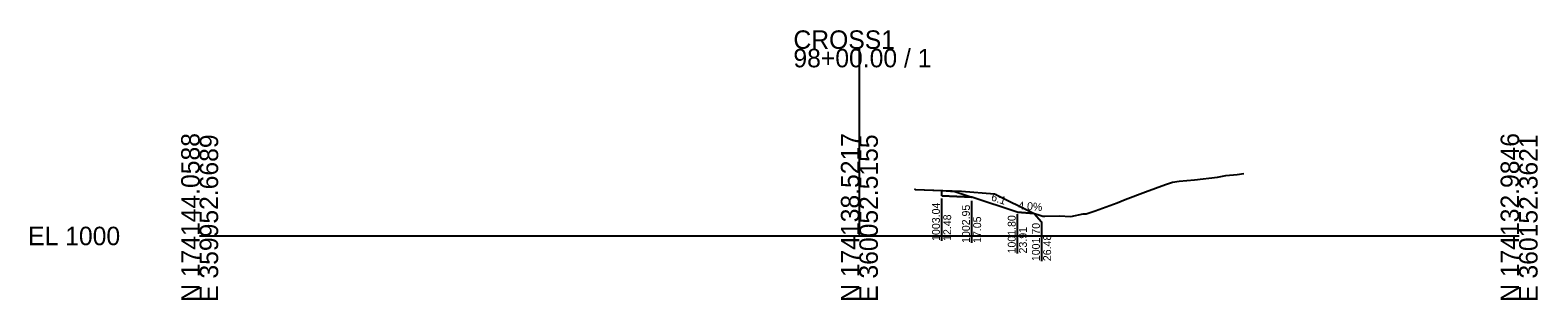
# Model space of a CAD drawing. Extents: x -26 to 1403, y -10 to 11027.
# Drawn here: x 1174.3 to 1402.8, y 1490.3 to 1531.2 of the extents above; entities that cross this region are included whole.
import ezdxf

# ---------------------------------------------------------------- set-up
doc = ezdxf.new("R2010")
doc.units = 0
for name, color, linetype in [('Default', 7, 'Continuous'), ('P_E_XS_Ground', 7, 'Continuous'), ('P_XS', 7, 'Continuous'), ('P_XS_EAR_CommonGrnd', 7, 'Continuous'), ('P_XS_Lane', 7, 'Continuous'), ('P_XS_Rock', 7, 'Continuous')]:
    doc.layers.add(name, color=color, linetype=linetype)

msp = doc.modelspace()

# ---------------------------------------------------------------- linework, layer by layer
at = {"layer": 'Default'}
for p, q in [((1300, 1500), (1300, 1528.38)), ((1200, 1500), (1300, 1500)), ((1300, 1500), (1400, 1500))]:
    msp.add_line(p, q, dxfattribs=at)
at = {"layer": 'P_E_XS_Ground'}
for p, q in [((1348.46, 1508.3), (1350.79, 1508.52)), ((1350.79, 1508.52), (1354.29, 1508.91)), ((1354.29, 1508.91), (1355.53, 1509.19)), ((1355.53, 1509.19), (1357.25, 1509.31)), ((1357.25, 1509.31), (1358.25, 1509.46)), ((1308.48, 1507.07), (1308.35, 1507.08)), ((1308.48, 1507.07), (1315.5, 1506.79)), ((1315.5, 1506.79), (1320.5, 1506.39)), ((1320.5, 1506.39), (1326.48, 1503.4)), ((1340.27, 1505.55), (1343.39, 1506.71)), ((1343.39, 1506.71), (1346.42, 1507.81)), ((1346.42, 1507.81), (1347.45, 1508.18)), ((1347.45, 1508.18), (1348.46, 1508.3)), ((1334.4, 1503.38), (1335.74, 1503.83)), ((1335.74, 1503.83), (1339.07, 1505.04)), ((1339.07, 1505.04), (1340.27, 1505.55)), ((1326.48, 1503.4), (1327.06, 1503.23)), ((1327.06, 1503.23), (1327.79, 1502.99)), ((1327.79, 1502.99), (1328.13, 1502.99)), ((1328.13, 1502.99), (1330.27, 1503.04)), ((1330.27, 1503.04), (1332.06, 1502.95)), ((1332.06, 1502.95), (1333.9, 1503.36)), ((1333.9, 1503.36), (1334.4, 1503.38))]:
    msp.add_line(p, q, dxfattribs=at)
at = {"layer": 'P_XS'}
for p, q in [((1308.48, 1507.07), (1312.48, 1506.91)), ((1312.48, 1506.91), (1314.48, 1506.75)), ((1314.48, 1506.75), (1317.05, 1505.89))]:
    msp.add_line(p, q, dxfattribs=at)
at = {"layer": 'P_XS_EAR_CommonGrnd'}
msp.add_lwpolyline([(1312.48, 1506.07), (1312.48, 1506.91), (1315.5, 1506.79), (1320.5, 1506.39), (1326.48, 1503.4), (1323.91, 1503.6), (1317.05, 1505.89)], close=True, dxfattribs=at)
at = {"layer": 'P_XS_Lane'}
for p, q in [((1312.48, 1506.07), (1312.48, 1506.91)), ((1312.48, 1506.07), (1317.05, 1505.89)), ((1323.91, 1503.6), (1317.05, 1505.89)), ((1323.91, 1503.6), (1326.48, 1503.4))]:
    msp.add_line(p, q, dxfattribs=at)
at = {"layer": 'P_XS_Rock'}
for p, q in [((1312.46, 1505.69), (1312.46, 1499.25)), ((1317, 1505.31), (1317, 1498.94)), ((1323.94, 1503.31), (1323.94, 1497.35)), ((1326.48, 1503.4), (1327.61, 1502.14)), ((1327.61, 1502.14), (1327.61, 1496.18))]:
    msp.add_line(p, q, dxfattribs=at)

# ---------------------------------------------------------------- texts
at = {"layer": 'Default'}
for s, p in [('CROSS1', (1290, 1528.38)), ('98+00.00 / 1', (1290, 1525.58)), ('EL 1000', (1174, 1498.6))]:
    msp.add_text(s, height=2.8, dxfattribs=at).set_placement(p)
for s, p in [('N 174144.0588', (1200, 1490)), ('E 359952.6689', (1202.8, 1490)), ('N 174138.5217', (1300, 1490)), ('E 360052.5155', (1302.8, 1490)), ('N 174132.9846', (1400, 1490)), ('E 360152.3621', (1402.8, 1490))]:
    msp.add_text(s, height=2.8, rotation=90, dxfattribs=at).set_placement(p)
at = {"layer": 'P_XS_Rock'}
for s, rotation, p in [('6:1', 341.5651, (1319.88, 1505.42)), ('1003.04', 90, (1312.21, 1499.25)), ('1002.95', 90, (1316.75, 1498.94)), ('4.0%', 355.4261, (1324.04, 1504.06)), ('12.48', 90, (1313.91, 1499.25)), ('17.05', 90, (1318.45, 1498.94)), ('1001.80', 90, (1323.69, 1497.35)), ('1001.70', 90, (1327.36, 1496.18)), ('23.91', 90, (1325.39, 1497.35)), ('26.48', 90, (1329.06, 1496.18))]:
    msp.add_text(s, height=1.2, rotation=rotation, dxfattribs=at).set_placement(p)

doc.saveas('drawing.dxf')
